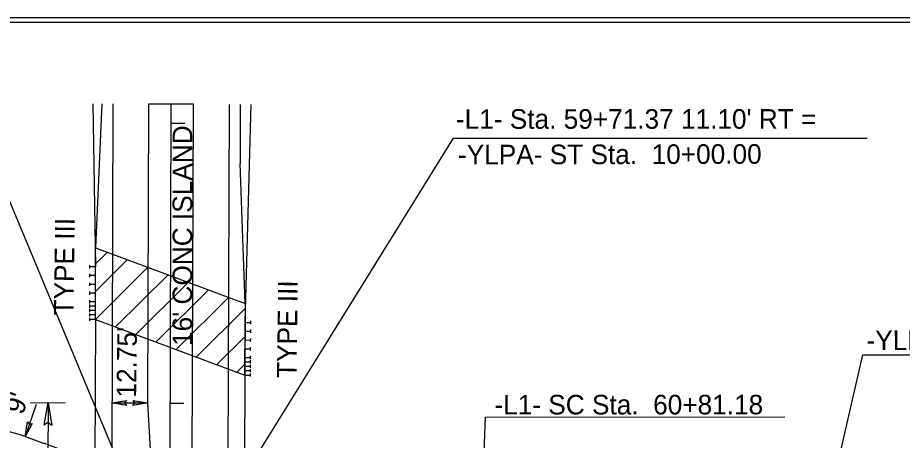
# Model space of a CAD drawing. Extents: x 573813 to 575363, y -54752 to -53123.
# Drawn here: x 574835.8 to 574930.6, y -54493.3 to -54448 of the extents above; entities that cross this region are included whole.
import ezdxf

# ---------------------------------------------------------------- set-up
doc = ezdxf.new("R2010")
doc.units = 0
for name, color, linetype in [('Exist CMT EOP', 7, 'Continuous'), ('Prop Approach Slab', 7, 'Continuous'), ('Prop Approach Slab Hatching', 7, 'Continuous'), ('Prop Conc 5in Monolithic Surface Mount Island', 7, 'Continuous'), ('Prop Dimension', 7, 'Continuous'), ('Prop Dimension Text', 7, 'Continuous'), ('Prop EOT', 7, 'Continuous'), ('Prop Guardrail', 7, 'Continuous'), ('Prop Horizontal Alignment', 7, 'Continuous'), ('Prop Horizontal Alignment Station Label', 7, 'Continuous'), ('Prop Horizontal Alignment Tick Small', 7, 'Continuous'), ('Prop Paved Shoulder', 7, 'Continuous'), ('Prop Roadway Bridge', 7, 'Continuous'), ('Prop Structure Anchor Unit CELL', 7, 'Continuous'), ('Prop Terminator CELL', 7, 'Continuous'), ('Sheet Border Standard 30in CELL', 7, 'Continuous'), ('Sheet Plot Border Inside CELL', 7, 'Continuous')]:
    doc.layers.add(name, color=color, linetype=linetype)

msp = doc.modelspace()

# ---------------------------------------------------------------- linework, layer by layer
at = {"layer": 'Exist CMT EOP'}
for points in [[(574813.01, -54490.031), (574824.433, -54494.189), (574838.567, -54499.094), (574853.668, -54504.441), (574867.599, -54509.431), (574881.004, -54513.824), (574895.195, -54518.43), (574909.355, -54523.036), (574924.041, -54527.744), (574938.327, -54532.116), (574953.438, -54536.77), (574966.785, -54540.638), (574967.019, -54540.706)], [(574811.749, -54491.023), (574824.507, -54495.581), (574838.708, -54500.463), (574852.937, -54505.498), (574866.511, -54510.153), (574881.429, -54515.234), (574895.441, -54519.841), (574909.744, -54524.513), (574923.562, -54528.898), (574937.859, -54533.312), (574952.039, -54537.636), (574965.884, -54541.599)]]:
    msp.add_spline(points, degree=3, dxfattribs=at)
at = {"layer": 'Prop Approach Slab'}
for p, q in [((574844.126, -54480.349), (574844.151, -54472.677)), ((574844.151, -54472.677), (574860.181, -54478.637)), ((574860.181, -54478.637), (574860.156, -54486.309))]:
    msp.add_line(p, q, dxfattribs=at)
at = {"layer": 'Prop Approach Slab Hatching'}
for p, q in [((574844.145, -54474.409), (574845.416, -54473.147)), ((574844.126, -54480.349), (574849.752, -54474.759)), ((574844.135, -54477.379), (574847.584, -54473.953)), ((574846.294, -54481.155), (574851.92, -54475.565)), ((574848.462, -54481.961), (574854.089, -54476.372)), ((574850.63, -54482.767), (574856.257, -54477.178)), ((574852.798, -54483.573), (574858.425, -54477.984)), ((574854.967, -54484.38), (574860.179, -54479.201)), ((574857.135, -54485.186), (574860.17, -54482.171)), ((574859.303, -54485.992), (574860.16, -54485.141))]:
    msp.add_line(p, q, dxfattribs=at)
at = {"layer": 'Prop Conc 5in Monolithic Surface Mount Island'}
for p, q in [((574849.827, -54457.286), (574849.721, -54489.306)), ((574854.627, -54457.306), (574849.827, -54457.286)), ((574854.027, -54638.249), (574854.627, -54457.306)), ((574849.721, -54489.306), (574853.122, -54549.318))]:
    msp.add_line(p, q, dxfattribs=at)
at = {"layer": 'Prop Dimension'}
for p, q in [((574837.799, -54489.485), (574836.594, -54492.887)), ((574837.122, -54489.265), (574840.876, -54489.277)), ((574839.05, -54489.271), (574838.851, -54549.271)), ((574845.896, -54489.294), (574849.721, -54489.306))]:
    msp.add_line(p, q, dxfattribs=at)
at = {"layer": 'Prop EOT'}
for p, q in [((574846.002, -54457.27), (574845.402, -54638.23)), ((574858.452, -54457.322), (574857.852, -54638.258))]:
    msp.add_line(p, q, dxfattribs=at)
msp.add_spline([(574827.632, -54492.501), (574827.823, -54492.571), (574828.013, -54492.64), (574828.203, -54492.709), (574828.393, -54492.779), (574828.584, -54492.848), (574828.774, -54492.917), (574828.964, -54492.987), (574829.155, -54493.056), (574829.345, -54493.125), (574829.535, -54493.194), (574829.725, -54493.264), (574829.916, -54493.333), (574830.106, -54493.402), (574830.296, -54493.471), (574830.487, -54493.541), (574830.677, -54493.61), (574830.867, -54493.679), (574831.058, -54493.748), (574831.248, -54493.817), (574831.438, -54493.887), (574831.628, -54493.956), (574831.819, -54494.025), (574832.009, -54494.094), (574832.199, -54494.163), (574832.39, -54494.233), (574832.58, -54494.302), (574832.77, -54494.371), (574832.961, -54494.44), (574833.151, -54494.509), (574833.341, -54494.578), (574833.531, -54494.648), (574833.722, -54494.717), (574833.912, -54494.786), (574834.102, -54494.855), (574834.293, -54494.924), (574834.483, -54494.993), (574834.673, -54495.062), (574834.864, -54495.131), (574835.054, -54495.2), (574835.244, -54495.269), (574835.435, -54495.339), (574835.625, -54495.408), (574835.815, -54495.477), (574836.006, -54495.546), (574836.196, -54495.615), (574836.386, -54495.684), (574836.577, -54495.753), (574836.767, -54495.822), (574836.957, -54495.891), (574837.148, -54495.96), (574837.338, -54496.029), (574837.528, -54496.098), (574837.719, -54496.167), (574837.909, -54496.236), (574838.099, -54496.305), (574838.29, -54496.374), (574838.48, -54496.443), (574838.67, -54496.512), (574838.861, -54496.58), (574839.051, -54496.649), (574839.241, -54496.718), (574839.432, -54496.787), (574839.622, -54496.856), (574839.812, -54496.925), (574840.003, -54496.994), (574840.193, -54497.063), (574840.383, -54497.132), (574840.574, -54497.201), (574840.764, -54497.269), (574840.954, -54497.338), (574841.145, -54497.407), (574841.335, -54497.476), (574841.526, -54497.545), (574841.716, -54497.614)], degree=3, dxfattribs=at)
at = {"layer": 'Prop Guardrail'}
for p, q in [((574843.853, -54457.261), (574844.144, -54474.724)), ((574860.174, -54480.684), (574860.826, -54457.332))]:
    msp.add_line(p, q, dxfattribs=at)
at = {"layer": 'Prop Horizontal Alignment'}
msp.add_line((574852.227, -54457.296), (574851.627, -54638.244), dxfattribs=at)
at = {"layer": 'Prop Horizontal Alignment Station Label'}
for p, q in [((574854.774, -54505.656), (574882.514, -54460.933)), ((574882.514, -54460.933), (574926.83, -54460.926)), ((574852.057, -54508.714), (574833.244, -54463.628)), ((574918.924, -54516.847), (574926.364, -54484.135)), ((574926.364, -54484.135), (574962.453, -54484.164)), ((574884.854, -54519.439), (574885.932, -54490.818)), ((574885.932, -54490.818), (574918.003, -54490.788))]:
    msp.add_line(p, q, dxfattribs=at)
at = {"layer": 'Prop Horizontal Alignment Tick Small'}
for p, q in [((574852.22, -54459.315), (574853.72, -54459.32)), ((574852.121, -54489.314), (574853.621, -54489.319))]:
    msp.add_line(p, q, dxfattribs=at)
at = {"layer": 'Prop Paved Shoulder'}
for p, q in [((574844.819, -54457.265), (574844.151, -54472.677)), ((574859.652, -54457.327), (574859.631, -54463.635)), ((574860.181, -54478.637), (574859.631, -54463.635))]:
    msp.add_line(p, q, dxfattribs=at)
for points in [[(574836.594, -54492.887), (574836.336, -54492.808), (574836.077, -54492.73), (574835.819, -54492.651), (574835.56, -54492.572), (574835.302, -54492.494), (574835.044, -54492.415), (574834.785, -54492.336), (574834.527, -54492.258), (574834.268, -54492.179), (574834.01, -54492.1), (574833.752, -54492.022), (574833.493, -54491.943), (574833.235, -54491.864), (574832.977, -54491.785), (574832.718, -54491.706), (574832.46, -54491.628), (574832.201, -54491.549), (574831.943, -54491.47), (574831.685, -54491.391), (574831.426, -54491.312), (574831.168, -54491.234), (574830.91, -54491.155), (574830.651, -54491.076), (574830.393, -54490.997), (574830.134, -54490.918), (574829.876, -54490.839), (574829.618, -54490.76), (574829.359, -54490.681), (574829.101, -54490.602), (574828.842, -54490.523), (574828.584, -54490.444), (574828.326, -54490.365), (574828.067, -54490.286), (574827.809, -54490.207), (574827.55, -54490.128), (574827.292, -54490.049), (574827.034, -54489.97), (574826.775, -54489.891), (574826.517, -54489.812), (574826.258, -54489.733), (574826, -54489.654), (574825.742, -54489.575), (574825.483, -54489.496), (574825.225, -54489.417), (574824.966, -54489.338), (574824.708, -54489.259), (574824.45, -54489.18), (574824.191, -54489.1), (574823.933, -54489.021), (574823.674, -54488.942), (574823.416, -54488.863), (574823.158, -54488.784), (574822.899, -54488.705), (574822.641, -54488.625), (574822.382, -54488.546), (574822.124, -54488.467), (574821.865, -54488.388), (574821.607, -54488.309), (574821.349, -54488.229), (574821.09, -54488.15), (574820.832, -54488.071), (574820.573, -54487.992), (574820.315, -54487.912), (574820.057, -54487.833), (574819.798, -54487.754), (574819.54, -54487.675), (574819.281, -54487.595), (574819.023, -54487.516), (574818.764, -54487.437), (574818.506, -54487.357), (574818.248, -54487.278), (574817.989, -54487.199), (574817.731, -54487.119), (574817.472, -54487.04)], [(574836.594, -54492.887), (574836.736, -54492.939), (574836.926, -54493.008), (574837.117, -54493.077), (574837.307, -54493.146), (574837.497, -54493.215), (574837.687, -54493.284), (574837.878, -54493.352), (574838.068, -54493.421), (574838.258, -54493.49), (574838.448, -54493.559), (574838.638, -54493.628), (574838.829, -54493.697), (574839.019, -54493.766), (574839.209, -54493.835), (574839.399, -54493.904), (574839.59, -54493.973), (574839.78, -54494.042), (574839.97, -54494.111), (574840.16, -54494.18), (574840.351, -54494.248), (574840.541, -54494.317), (574840.731, -54494.386), (574840.921, -54494.455), (574841.112, -54494.524), (574841.302, -54494.593), (574841.492, -54494.662), (574841.682, -54494.73), (574841.873, -54494.799), (574842.063, -54494.868), (574842.253, -54494.937), (574842.443, -54495.006), (574842.634, -54495.074)]]:
    msp.add_spline(points, degree=3, dxfattribs=at)
at = {"layer": 'Prop Roadway Bridge'}
for p, q in [((574844.126, -54480.349), (574843.782, -54584.035)), ((574844.126, -54480.349), (574860.156, -54486.309)), ((574860.156, -54486.309), (574859.812, -54589.995))]:
    msp.add_line(p, q, dxfattribs=at)
at = {"layer": 'Prop Structure Anchor Unit CELL'}
for p, q in [((574843.544, -54474.894), (574843.545, -54474.55)), ((574844.144, -54474.724), (574843.544, -54474.722)), ((574844.126, -54480.349), (574844.144, -54474.724)), ((574843.54, -54475.831), (574843.542, -54475.488)), ((574844.141, -54475.661), (574843.541, -54475.659)), ((574843.537, -54476.769), (574843.539, -54476.425)), ((574844.138, -54476.599), (574843.538, -54476.597)), ((574843.534, -54477.706), (574843.535, -54477.362)), ((574844.135, -54477.536), (574843.535, -54477.534)), ((574843.531, -54478.644), (574843.532, -54478.3)), ((574844.132, -54478.474), (574843.532, -54478.472)), ((574843.528, -54479.581), (574843.529, -54479.237)), ((574844.129, -54479.411), (574843.529, -54479.409)), ((574843.53, -54479.112), (574843.531, -54478.769)), ((574844.13, -54478.943), (574843.53, -54478.941)), ((574843.525, -54480.519), (574843.526, -54480.175)), ((574843.526, -54480.05), (574843.528, -54479.706)), ((574844.126, -54480.349), (574843.526, -54480.347)), ((574844.127, -54479.88), (574843.527, -54479.878)), ((574860.156, -54486.309), (574860.174, -54480.684)), ((574860.174, -54480.684), (574860.774, -54480.686)), ((574860.774, -54480.858), (574860.775, -54480.514)), ((574860.171, -54481.622), (574860.771, -54481.624)), ((574860.771, -54481.795), (574860.772, -54481.452)), ((574860.168, -54482.559), (574860.768, -54482.561)), ((574860.765, -54483.67), (574860.766, -54483.327)), ((574860.768, -54482.733), (574860.769, -54482.389)), ((574860.165, -54483.497), (574860.765, -54483.499)), ((574860.761, -54484.608), (574860.763, -54484.264)), ((574860.161, -54484.903), (574860.76, -54484.905)), ((574860.162, -54484.434), (574860.762, -54484.436)), ((574860.758, -54485.545), (574860.76, -54485.202)), ((574860.76, -54485.077), (574860.761, -54484.733)), ((574860.157, -54485.84), (574860.757, -54485.842)), ((574860.159, -54485.372), (574860.759, -54485.374)), ((574860.755, -54486.483), (574860.756, -54486.139)), ((574860.757, -54486.014), (574860.758, -54485.671)), ((574860.156, -54486.309), (574860.756, -54486.311))]:
    msp.add_line(p, q, dxfattribs=at)
at = {"layer": 'Prop Terminator CELL'}
for points in [[(574838.623, -54491.7), (574839.05, -54489.271), (574839.474, -54491.716), (574839.043, -54491.404)], [(574847.45, -54489.567), (574845.896, -54489.294), (574847.461, -54489.023), (574847.261, -54489.298)], [(574848.167, -54489.033), (574849.721, -54489.306), (574848.156, -54489.578), (574848.356, -54489.302)], [(574837.366, -54491.51), (574836.594, -54492.887), (574836.855, -54491.321), (574837.05, -54491.6)]]:
    msp.add_lwpolyline(points, close=True, dxfattribs=at)
at = {"layer": 'Sheet Border Standard 30in CELL'}
msp.add_lwpolyline([(575003.131, -54448.543), (574703.131, -54448.543), (574703.131, -54658.543), (575003.131, -54658.543)], close=True, dxfattribs=at)
at = {"layer": 'Sheet Plot Border Inside CELL'}
msp.add_lwpolyline([(575005.631, -54448.033), (574672.331, -54448.033), (574672.331, -54659.053), (575005.631, -54659.053)], close=True, dxfattribs=at)

# ---------------------------------------------------------------- texts
at = {"layer": 'Prop Dimension Text'}
for s, rotation, p in [("16' CONC ISLAND", 89.99341, (574854.503, -54483.199)), ('TYPE III', 89.23189, (574841.776, -54479.947)), ('TYPE III', 89.23189, (574865.675, -54486.638)), ("12.75'", 89.23189, (574848.49, -54488.741)), ("9'", 69.96688, (574836.336, -54490.662))]:
    msp.add_text(s, height=2.1, rotation=rotation, dxfattribs=at).set_placement(p)
at = {"layer": 'Prop Horizontal Alignment Station Label'}
for s, rotation, p in [("-L1- Sta. 59+71.37 11.10' RT =", 0.00957, (574882.764, -54459.934)), ('-YLPA- ST Sta.  10+00.00', 0.1392, (574882.989, -54463.756)), ('-YLPA- SC Sta.  12+20.00', 0.15901, (574926.768, -54483.647)), ('-L1- SC Sta.  60+81.18', 0.02369, (574886.89, -54490.54))]:
    msp.add_text(s, height=2.1, rotation=rotation, dxfattribs=at).set_placement(p)

doc.saveas('drawing.dxf')
